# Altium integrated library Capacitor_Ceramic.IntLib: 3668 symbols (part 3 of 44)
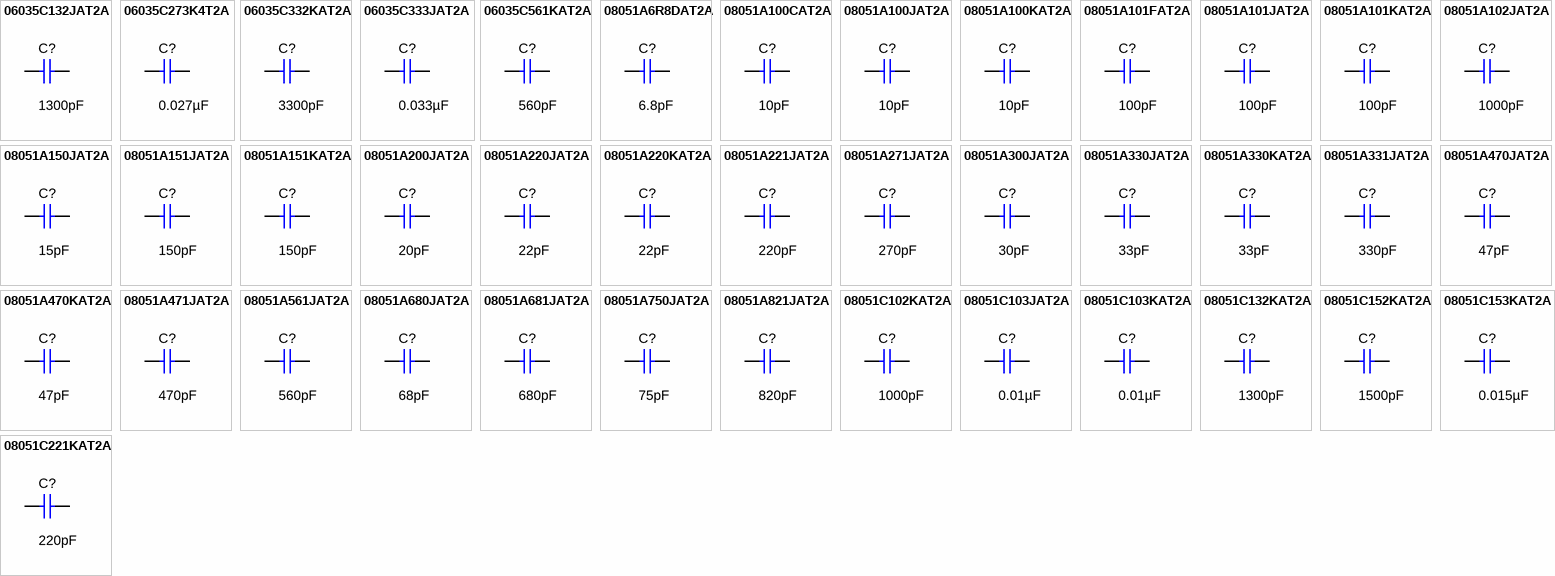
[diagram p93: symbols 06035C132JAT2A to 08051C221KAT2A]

## 06035C332KAT2A
designator C?  ValueDisplayed: 3300pF  (hidden comment: 06035C332KAT2A)
CAP, CERM, 3300 pF, 50 V,+/- 10%, X7R, 0603; Manufacturer: AVX; Polarized: N; CompType: Capacitor; Value: 3300pF; U/M: EA; Cap_F: 0.0000000033; Tolerance_%: 10; VDC_V: 50; Value2: 50V; TaMin_C: -55; TaMax_C: 125; Cap_Case: 0603; SizeArea_mm2: 1.28; SizeAreaWB_mm2: 4.68; SizeX_mm: 1.6; SizeY_mm: 0.8; SizeZ_mm: 1; AEC Category: Q200; Green_Lifecycle: Active; Green_REACh: Passed
signal-integrity model Cap
simulation model Cap
footprint 0603
footprint 0603M
footprint 0603L
footprint 0603_HV
footprint 0603S
pins: 1, 2

## 06035C333JAT2A
designator C?  ValueDisplayed: 0.033µF  (hidden comment: 06035C333JAT2A)
CAP, CERM, 0.033 µF, 50 V,+/- 5%, X7R, 0603; Manufacturer: AVX; Polarized: N; CompType: Capacitor; Value: 0.033uF; U/M: EA; Cap_F: 0.000000033; Tolerance_%: 5; VDC_V: 50; Value2: 50V; TaMin_C: -55; TaMax_C: 125; Cap_Case: 0603; SizeArea_mm2: 1.28; SizeAreaWB_mm2: 4.68; SizeX_mm: 1.6; SizeY_mm: 0.8; SizeZ_mm: 1; AEC Category: Q200; Green_Lifecycle: Active; Green_REACh: Passed
signal-integrity model Cap
simulation model Cap
footprint 0603
footprint 0603M
footprint 0603L
footprint 0603_HV
footprint 0603S
pins: 1, 2

## 06035C561KAT2A
designator C?  ValueDisplayed: 560pF  (hidden comment: 06035C561KAT2A)
CAP, CERM, 560 pF, 50 V,+/- 10%, X7R, 0603; Manufacturer: AVX; Polarized: N; CompType: Capacitor; Value: 560pF; U/M: EA; Cap_F: 0.00000000056; Tolerance_%: 10; VDC_V: 50; Value2: 50V; TaMin_C: -55; TaMax_C: 125; Cap_Case: 0603; SizeArea_mm2: 1.28; SizeAreaWB_mm2: 4.68; SizeX_mm: 1.6; SizeY_mm: 0.8; SizeZ_mm: 1; AEC Category: Q200; Green_Lifecycle: Not Set; Green_REACh: Incomplete
signal-integrity model Cap
simulation model Cap
footprint 0603
footprint 0603M
footprint 0603L
footprint 0603_HV
footprint 0603S
pins: 1, 2

## 08051A6R8DAT2A
designator C?  ValueDisplayed: 6.8pF  (hidden comment: 08051A6R8DAT2A)
CAP, CERM, 6.8 pF, 100 V,+/- 5%, C0G/NP0, 0805; Manufacturer: AVX; Polarized: N; CompType: Capacitor; Value: 6.8pF; U/M: EA; Cap_F: 0.0000000000068; Tolerance_%: 5; ESR_ohm: 2.045; Value1: 2.045 ohm; VDC_V: 100; Value2: 100V; TaMin_C: -55; TaMax_C: 125; Cap_Case: 0805; SizeArea_mm2: 2.5; SizeAreaWB_mm2: 6.75; SizeX_mm: 2; SizeY_mm: 1.25; SizeZ_mm: 1.45; AEC Category: Q200; Green_Lifecycle: Not Set; Green_REACh: Incomplete
signal-integrity model Cap
simulation model Cap
footprint 0805_HV
footprint 0805_HV1
footprint 0805
footprint 0805M
footprint 0805L
pins: 1, 2

## 08051A100CAT2A
designator C?  ValueDisplayed: 10pF  (hidden comment: 08051A100CAT2A)
CAP, CERM, 10 pF, 100 V,+/- 5%, C0G/NP0, 0805; Manufacturer: AVX; Polarized: N; CompType: Capacitor; Value: 10pF; U/M: EA; Cap_F: 0.00000000001; Tolerance_%: 5; ESR_ohm: 1.561; Value1: 1.561 ohm; VDC_V: 100; Value2: 100V; TaMin_C: -55; TaMax_C: 125; Cap_Case: 0805; SizeArea_mm2: 2.5; SizeAreaWB_mm2: 6.75; SizeX_mm: 2; SizeY_mm: 1.25; SizeZ_mm: 1.45; AEC Category: Q200; Green_Lifecycle: Not Set; Green_REACh: Incomplete
signal-integrity model Cap
simulation model Cap
footprint 0805_HV
footprint 0805_HV1
footprint 0805
footprint 0805M
footprint 0805L
pins: 1, 2

## 08051A100JAT2A
designator C?  ValueDisplayed: 10pF  (hidden comment: 08051A100JAT2A)
CAP, CERM, 10 pF, 100 V,+/- 5%, C0G/NP0, 0805; Manufacturer: AVX; Polarized: N; CompType: Capacitor; Value: 10pF; U/M: EA; Cap_F: 0.00000000001; Tolerance_%: 5; ESR_ohm: 1.561; Value1: 1.561 ohm; VDC_V: 100; Value2: 100V; TaMin_C: -55; TaMax_C: 125; Cap_Case: 0805; SizeArea_mm2: 2.5; SizeAreaWB_mm2: 6.75; SizeX_mm: 2; SizeY_mm: 1.25; SizeZ_mm: 1.45; AEC Category: Q200; Green_Lifecycle: Not Set; Green_REACh: Incomplete
signal-integrity model Cap
simulation model Cap
footprint 0805_HV
footprint 0805_HV1
footprint 0805
footprint 0805M
footprint 0805L
pins: 1, 2

## 08051A100KAT2A
designator C?  ValueDisplayed: 10pF  (hidden comment: 08051A100KAT2A)
CAP, CERM, 10 pF, 100 V,+/- 10%, C0G/NP0, 0805; Manufacturer: AVX; Polarized: N; CompType: Capacitor; Value: 10pF; U/M: EA; Cap_F: 0.00000000001; Tolerance_%: 10; ESR_ohm: 1.561; Value1: 1.561 ohm; VDC_V: 100; Value2: 100V; TaMin_C: -55; TaMax_C: 125; Cap_Case: 0805; SizeArea_mm2: 2.5; SizeAreaWB_mm2: 6.75; SizeX_mm: 2; SizeY_mm: 1.25; SizeZ_mm: 1.45; AEC Category: Q200; Green_Lifecycle: Not Set; Green_REACh: Incomplete
signal-integrity model Cap
simulation model Cap
footprint 0805_HV
footprint 0805_HV1
footprint 0805
footprint 0805M
footprint 0805L
pins: 1, 2

## 08051A101FAT2A
designator C?  ValueDisplayed: 100pF  (hidden comment: 08051A101FAT2A)
CAP, CERM, 100 pF, 100 V,+/- 1%, C0G/NP0, 0805; Manufacturer: AVX; Polarized: N; CompType: Capacitor; Value: 100pF; U/M: EA; Cap_F: 0.0000000001; Tolerance_%: 1; ESR_ohm: 0.356; Value1: 0.356 ohm; VDC_V: 100; Value2: 100V; TaMin_C: -55; TaMax_C: 125; Cap_Case: 0805; SizeArea_mm2: 2.5; SizeAreaWB_mm2: 6.75; SizeX_mm: 2; SizeY_mm: 1.25; SizeZ_mm: 1.45; AEC Category: Q200; Green_Lifecycle: Not Set; Green_REACh: Incomplete
signal-integrity model Cap
simulation model Cap
footprint 0805_HV
footprint 0805_HV1
footprint 0805
footprint 0805M
footprint 0805L
pins: 1, 2

## 08051A101JAT2A
designator C?  ValueDisplayed: 100pF  (hidden comment: 08051A101JAT2A)
CAP, CERM, 100 pF, 100 V,+/- 5%, C0G/NP0, 0805; Manufacturer: AVX; Polarized: N; CompType: Capacitor; Value: 100pF; U/M: EA; Cap_F: 0.0000000001; Tolerance_%: 5; ESR_ohm: 0.356; Value1: 0.356 ohm; VDC_V: 100; Value2: 100V; TaMin_C: -55; TaMax_C: 125; Cap_Case: 0805; SizeArea_mm2: 2.5; SizeAreaWB_mm2: 6.75; SizeX_mm: 2; SizeY_mm: 1.25; SizeZ_mm: 1.45; AEC Category: Q200; Green_Lifecycle: Not Set; Green_REACh: Incomplete
signal-integrity model Cap
simulation model Cap
footprint 0805_HV
footprint 0805_HV1
footprint 0805
footprint 0805M
footprint 0805L
pins: 1, 2

## 08051A101KAT2A
designator C?  ValueDisplayed: 100pF  (hidden comment: 08051A101KAT2A)
CAP, CERM, 100 pF, 100 V,+/- 10%, C0G/NP0, 0805; Manufacturer: AVX; Polarized: N; CompType: Capacitor; Value: 100pF; U/M: EA; Cap_F: 0.0000000001; Tolerance_%: 10; ESR_ohm: 0.356; Value1: 0.356 ohm; VDC_V: 100; Value2: 100V; TaMin_C: -55; TaMax_C: 125; Cap_Case: 0805; SizeArea_mm2: 2.5; SizeAreaWB_mm2: 6.75; SizeX_mm: 2; SizeY_mm: 1.25; SizeZ_mm: 1.45; AEC Category: Q200; Green_Lifecycle: Not Set; Green_REACh: Incomplete
signal-integrity model Cap
simulation model Cap
footprint 0805_HV
footprint 0805_HV1
footprint 0805
footprint 0805M
footprint 0805L
pins: 1, 2

## 08051A102JAT2A
designator C?  ValueDisplayed: 1000pF  (hidden comment: 08051A102JAT2A)
CAP, CERM, 1000 pF, 100 V,+/- 5%, C0G/NP0, 0805; Manufacturer: AVX; Polarized: N; CompType: Capacitor; Value: 1000pF; U/M: EA; Cap_F: 0.000000001; Tolerance_%: 5; ESR_ohm: 0.112; Value1: 0.112 ohm; VDC_V: 100; Value2: 100V; TaMin_C: -55; TaMax_C: 125; Cap_Case: 0805; SizeArea_mm2: 2.5; SizeAreaWB_mm2: 6.75; SizeX_mm: 2; SizeY_mm: 1.25; SizeZ_mm: 1.45; AEC Category: Q200; Green_Lifecycle: Not Set; Green_REACh: Incomplete
signal-integrity model Cap
simulation model Cap
footprint 0805_HV
footprint 0805_HV1
footprint 0805
footprint 0805M
footprint 0805L
pins: 1, 2

## 08051A150JAT2A
designator C?  ValueDisplayed: 15pF  (hidden comment: 08051A150JAT2A)
CAP, CERM, 15 pF, 100 V,+/- 5%, C0G/NP0, 0805; Manufacturer: AVX; Polarized: N; CompType: Capacitor; Value: 15pF; U/M: EA; Cap_F: 0.000000000015; Tolerance_%: 5; ESR_ohm: 1.185; Value1: 1.185 ohm; VDC_V: 100; Value2: 100V; TaMin_C: -55; TaMax_C: 125; Cap_Case: 0805; SizeArea_mm2: 2.5; SizeAreaWB_mm2: 6.75; SizeX_mm: 2; SizeY_mm: 1.25; SizeZ_mm: 1.45; AEC Category: Q200; Green_Lifecycle: Not Set; Green_REACh: Incomplete
signal-integrity model Cap
simulation model Cap
footprint 0805_HV
footprint 0805_HV1
footprint 0805
footprint 0805M
footprint 0805L
pins: 1, 2

## 08051A151JAT2A
designator C?  ValueDisplayed: 150pF  (hidden comment: 08051A151JAT2A)
CAP, CERM, 150 pF, 100 V,+/- 5%, C0G/NP0, 0805; Manufacturer: AVX; Polarized: N; CompType: Capacitor; Value: 150pF; U/M: EA; Cap_F: 0.00000000015; Tolerance_%: 5; ESR_ohm: 0.279; Value1: 0.279 ohm; VDC_V: 100; Value2: 100V; TaMin_C: -55; TaMax_C: 125; Cap_Case: 0805; SizeArea_mm2: 2.5; SizeAreaWB_mm2: 6.75; SizeX_mm: 2; SizeY_mm: 1.25; SizeZ_mm: 1.45; AEC Category: Q200; Green_Lifecycle: Not Set; Green_REACh: Incomplete
signal-integrity model Cap
simulation model Cap
footprint 0805_HV
footprint 0805_HV1
footprint 0805
footprint 0805M
footprint 0805L
pins: 1, 2

## 08051A151KAT2A
designator C?  ValueDisplayed: 150pF  (hidden comment: 08051A151KAT2A)
CAP, CERM, 150 pF, 100 V,+/- 10%, C0G/NP0, 0805; Manufacturer: AVX; Polarized: N; CompType: Capacitor; Value: 150pF; U/M: EA; Cap_F: 0.00000000015; Tolerance_%: 10; ESR_ohm: 0.279; Value1: 0.279 ohm; VDC_V: 100; Value2: 100V; TaMin_C: -55; TaMax_C: 125; Cap_Case: 0805; SizeArea_mm2: 2.5; SizeAreaWB_mm2: 6.75; SizeX_mm: 2; SizeY_mm: 1.25; SizeZ_mm: 1.45; AEC Category: Q200; Green_Lifecycle: Not Set; Green_REACh: Incomplete
signal-integrity model Cap
simulation model Cap
footprint 0805_HV
footprint 0805_HV1
footprint 0805
footprint 0805M
footprint 0805L
pins: 1, 2

## 08051A200JAT2A
designator C?  ValueDisplayed: 20pF  (hidden comment: 08051A200JAT2A)
CAP, CERM, 20 pF, 100 V,+/- 5%, C0G/NP0, 0805; Manufacturer: AVX; Polarized: N; CompType: Capacitor; Value: 20pF; U/M: EA; Cap_F: 0.00000000002; Tolerance_%: 5; ESR_ohm: 0.92; Value1: 0.92 ohm; VDC_V: 100; Value2: 100V; TaMin_C: -55; TaMax_C: 125; Cap_Case: 0805; SizeArea_mm2: 2.5; SizeAreaWB_mm2: 6.75; SizeX_mm: 2; SizeY_mm: 1.25; SizeZ_mm: 1.45; AEC Category: Q200; Green_Lifecycle: Not Set; Green_REACh: Incomplete
signal-integrity model Cap
simulation model Cap
footprint 0805_HV
footprint 0805_HV1
footprint 0805
footprint 0805M
footprint 0805L
pins: 1, 2

## 08051A220JAT2A
designator C?  ValueDisplayed: 22pF  (hidden comment: 08051A220JAT2A)
CAP, CERM, 22 pF, 100 V,+/- 5%, C0G/NP0, 0805; Manufacturer: AVX; Polarized: N; CompType: Capacitor; Value: 22pF; U/M: EA; Cap_F: 0.000000000022; Tolerance_%: 5; ESR_ohm: 0.92; Value1: 0.92 ohm; VDC_V: 100; Value2: 100V; TaMin_C: -55; TaMax_C: 125; Cap_Case: 0805; SizeArea_mm2: 2.5; SizeAreaWB_mm2: 6.75; SizeX_mm: 2; SizeY_mm: 1.25; SizeZ_mm: 1.45; AEC Category: Q200; Green_Lifecycle: Not Set; Green_REACh: Incomplete
signal-integrity model Cap
simulation model Cap
footprint 0805_HV
footprint 0805_HV1
footprint 0805
footprint 0805M
footprint 0805L
pins: 1, 2

## 08051A220KAT2A
designator C?  ValueDisplayed: 22pF  (hidden comment: 08051A220KAT2A)
CAP, CERM, 22 pF, 100 V,+/- 10%, C0G/NP0, 0805; Manufacturer: AVX; Polarized: N; CompType: Capacitor; Value: 22pF; U/M: EA; Cap_F: 0.000000000022; Tolerance_%: 10; ESR_ohm: 0.92; Value1: 0.92 ohm; VDC_V: 100; Value2: 100V; TaMin_C: -55; TaMax_C: 125; Cap_Case: 0805; SizeArea_mm2: 2.5; SizeAreaWB_mm2: 6.75; SizeX_mm: 2; SizeY_mm: 1.25; SizeZ_mm: 1.45; AEC Category: Q200; Green_Lifecycle: Not Set; Green_REACh: Incomplete
signal-integrity model Cap
simulation model Cap
footprint 0805_HV
footprint 0805_HV1
footprint 0805
footprint 0805M
footprint 0805L
pins: 1, 2

## 08051A221JAT2A
designator C?  ValueDisplayed: 220pF  (hidden comment: 08051A221JAT2A)
CAP, CERM, 220 pF, 100 V,+/- 5%, C0G/NP0, 0805; Manufacturer: AVX; Polarized: N; CompType: Capacitor; Value: 220pF; U/M: EA; Cap_F: 0.00000000022; Tolerance_%: 5; ESR_ohm: 0.23; Value1: 0.23 ohm; VDC_V: 100; Value2: 100V; TaMin_C: -55; TaMax_C: 125; Cap_Case: 0805; SizeArea_mm2: 2.5; SizeAreaWB_mm2: 6.75; SizeX_mm: 2; SizeY_mm: 1.25; SizeZ_mm: 1.45; AEC Category: Q200; Green_Lifecycle: Not Set; Green_REACh: Incomplete
signal-integrity model Cap
simulation model Cap
footprint 0805_HV
footprint 0805_HV1
footprint 0805
footprint 0805M
footprint 0805L
pins: 1, 2

## 08051A271JAT2A
designator C?  ValueDisplayed: 270pF  (hidden comment: 08051A271JAT2A)
CAP, CERM, 270 pF, 100 V,+/- 5%, C0G/NP0, 0805; Manufacturer: AVX; Polarized: N; CompType: Capacitor; Value: 270pF; U/M: EA; Cap_F: 0.00000000027; Tolerance_%: 5; ESR_ohm: 0.208; Value1: 0.208 ohm; VDC_V: 100; Value2: 100V; TaMin_C: -55; TaMax_C: 125; Cap_Case: 0805; SizeArea_mm2: 2.5; SizeAreaWB_mm2: 6.75; SizeX_mm: 2; SizeY_mm: 1.25; SizeZ_mm: 1.45; AEC Category: Q200; Green_Lifecycle: Not Set; Green_REACh: Incomplete
signal-integrity model Cap
simulation model Cap
footprint 0805_HV
footprint 0805_HV1
footprint 0805
footprint 0805M
footprint 0805L
pins: 1, 2

## 08051A300JAT2A
designator C?  ValueDisplayed: 30pF  (hidden comment: 08051A300JAT2A)
CAP, CERM, 30 pF, 100 V,+/- 5%, C0G/NP0, 0805; Manufacturer: AVX; Polarized: N; CompType: Capacitor; Value: 30pF; U/M: EA; Cap_F: 0.00000000003; Tolerance_%: 5; ESR_ohm: 0.708; Value1: 0.708 ohm; VDC_V: 100; Value2: 100V; TaMin_C: -55; TaMax_C: 125; Cap_Case: 0805; SizeArea_mm2: 2.5; SizeAreaWB_mm2: 6.75; SizeX_mm: 2; SizeY_mm: 1.25; SizeZ_mm: 1.45; AEC Category: Q200; Green_Lifecycle: Not Set; Green_REACh: Incomplete
signal-integrity model Cap
simulation model Cap
footprint 0805_HV
footprint 0805_HV1
footprint 0805
footprint 0805M
footprint 0805L
pins: 1, 2

## 08051A330JAT2A
designator C?  ValueDisplayed: 33pF  (hidden comment: 08051A330JAT2A)
CAP, CERM, 33 pF, 100 V,+/- 5%, C0G/NP0, 0805; Manufacturer: AVX; Polarized: N; CompType: Capacitor; Value: 33pF; U/M: EA; Cap_F: 0.000000000033; Tolerance_%: 5; ESR_ohm: 0.708; Value1: 0.708 ohm; VDC_V: 100; Value2: 100V; TaMin_C: -55; TaMax_C: 125; Cap_Case: 0805; SizeArea_mm2: 2.5; SizeAreaWB_mm2: 6.75; SizeX_mm: 2; SizeY_mm: 1.25; SizeZ_mm: 1.45; AEC Category: Q200; Green_Lifecycle: Not Set; Green_REACh: Incomplete
signal-integrity model Cap
simulation model Cap
footprint 0805_HV
footprint 0805_HV1
footprint 0805
footprint 0805M
footprint 0805L
pins: 1, 2

## 08051A330KAT2A
designator C?  ValueDisplayed: 33pF  (hidden comment: 08051A330KAT2A)
CAP, CERM, 33 pF, 100 V,+/- 10%, C0G/NP0, 0805; Manufacturer: AVX; Polarized: N; CompType: Capacitor; Value: 33pF; U/M: EA; Cap_F: 0.000000000033; Tolerance_%: 10; ESR_ohm: 0.708; Value1: 0.708 ohm; VDC_V: 100; Value2: 100V; TaMin_C: -55; TaMax_C: 125; Cap_Case: 0805; SizeArea_mm2: 2.5; SizeAreaWB_mm2: 6.75; SizeX_mm: 2; SizeY_mm: 1.25; SizeZ_mm: 1.45; AEC Category: Q200; Green_Lifecycle: Not Set; Green_REACh: Incomplete
signal-integrity model Cap
simulation model Cap
footprint 0805_HV
footprint 0805_HV1
footprint 0805
footprint 0805M
footprint 0805L
pins: 1, 2

## 08051A331JAT2A
designator C?  ValueDisplayed: 330pF  (hidden comment: 08051A331JAT2A)
CAP, CERM, 330 pF, 100 V,+/- 5%, C0G/NP0, 0805; Manufacturer: AVX; Polarized: N; CompType: Capacitor; Value: 330pF; U/M: EA; Cap_F: 0.00000000033; Tolerance_%: 5; ESR_ohm: 0.185; Value1: 0.185 ohm; VDC_V: 100; Value2: 100V; TaMin_C: -55; TaMax_C: 125; Cap_Case: 0805; SizeArea_mm2: 2.5; SizeAreaWB_mm2: 6.75; SizeX_mm: 2; SizeY_mm: 1.25; SizeZ_mm: 1.45; AEC Category: Q200; Green_Lifecycle: Not Set; Green_REACh: Incomplete
signal-integrity model Cap
simulation model Cap
footprint 0805_HV
footprint 0805_HV1
footprint 0805
footprint 0805M
footprint 0805L
pins: 1, 2

## 08051A470JAT2A
designator C?  ValueDisplayed: 47pF  (hidden comment: 08051A470JAT2A)
CAP, CERM, 47 pF, 100 V,+/- 5%, C0G/NP0, 0805; Manufacturer: AVX; Polarized: N; CompType: Capacitor; Value: 47pF; U/M: EA; Cap_F: 0.000000000047; Tolerance_%: 5; ESR_ohm: 0.566; Value1: 0.566 ohm; VDC_V: 100; Value2: 100V; TaMin_C: -55; TaMax_C: 125; Cap_Case: 0805; SizeArea_mm2: 2.5; SizeAreaWB_mm2: 6.75; SizeX_mm: 2; SizeY_mm: 1.25; SizeZ_mm: 1.45; AEC Category: Q200; Green_Lifecycle: Active; Green_REACh: Passed
signal-integrity model Cap
simulation model Cap
footprint 0805_HV
footprint 0805_HV1
footprint 0805
footprint 0805M
footprint 0805L
pins: 1, 2

## 08051A470KAT2A
designator C?  ValueDisplayed: 47pF  (hidden comment: 08051A470KAT2A)
CAP, CERM, 47 pF, 100 V,+/- 10%, C0G/NP0, 0805; Manufacturer: AVX; Polarized: N; CompType: Capacitor; Value: 47pF; U/M: EA; Cap_F: 0.000000000047; Tolerance_%: 10; ESR_ohm: 0.566; Value1: 0.566 ohm; VDC_V: 100; Value2: 100V; TaMin_C: -55; TaMax_C: 125; Cap_Case: 0805; SizeArea_mm2: 2.5; SizeAreaWB_mm2: 6.75; SizeX_mm: 2; SizeY_mm: 1.25; SizeZ_mm: 1.45; AEC Category: Q200; Green_Lifecycle: Not Set; Green_REACh: Incomplete
signal-integrity model Cap
simulation model Cap
footprint 0805_HV
footprint 0805_HV1
footprint 0805
footprint 0805M
footprint 0805L
pins: 1, 2

## 08051A471JAT2A
designator C?  ValueDisplayed: 470pF  (hidden comment: 08051A471JAT2A)
CAP, CERM, 470 pF, 100 V,+/- 5%, C0G/NP0, 0805; Manufacturer: AVX; Polarized: N; CompType: Capacitor; Value: 470pF; U/M: EA; Cap_F: 0.00000000047; Tolerance_%: 5; ESR_ohm: 0.159; Value1: 0.159 ohm; VDC_V: 100; Value2: 100V; TaMin_C: -55; TaMax_C: 125; Cap_Case: 0805; SizeArea_mm2: 2.5; SizeAreaWB_mm2: 6.75; SizeX_mm: 2; SizeY_mm: 1.25; SizeZ_mm: 1.45; AEC Category: Q200; Green_Lifecycle: Active; Green_REACh: Passed
signal-integrity model Cap
simulation model Cap
footprint 0805_HV
footprint 0805_HV1
footprint 0805
footprint 0805M
footprint 0805L
pins: 1, 2

## 08051A561JAT2A
designator C?  ValueDisplayed: 560pF  (hidden comment: 08051A561JAT2A)
CAP, CERM, 560 pF, 100 V,+/- 5%, C0G/NP0, 0805; Manufacturer: AVX; Polarized: N; CompType: Capacitor; Value: 560pF; U/M: EA; Cap_F: 0.00000000056; Tolerance_%: 5; ESR_ohm: 0.147; Value1: 0.147 ohm; VDC_V: 100; Value2: 100V; TaMin_C: -55; TaMax_C: 125; Cap_Case: 0805; SizeArea_mm2: 2.5; SizeAreaWB_mm2: 6.75; SizeX_mm: 2; SizeY_mm: 1.25; SizeZ_mm: 1.45; AEC Category: Q200; Green_Lifecycle: Active; Green_REACh: Passed
signal-integrity model Cap
simulation model Cap
footprint 0805_HV
footprint 0805_HV1
footprint 0805
footprint 0805M
footprint 0805L
pins: 1, 2

## 08051A680JAT2A
designator C?  ValueDisplayed: 68pF  (hidden comment: 08051A680JAT2A)
CAP, CERM, 68 pF, 100 V,+/- 5%, C0G/NP0, 0805; Manufacturer: AVX; Polarized: N; CompType: Capacitor; Value: 68pF; U/M: EA; Cap_F: 0.000000000068; Tolerance_%: 5; ESR_ohm: 0.45; Value1: 0.45 ohm; VDC_V: 100; Value2: 100V; TaMin_C: -55; TaMax_C: 125; Cap_Case: 0805; SizeArea_mm2: 2.5; SizeAreaWB_mm2: 6.75; SizeX_mm: 2; SizeY_mm: 1.25; SizeZ_mm: 1.45; AEC Category: Q200; Green_Lifecycle: Not Set; Green_REACh: Incomplete
signal-integrity model Cap
simulation model Cap
footprint 0805_HV
footprint 0805_HV1
footprint 0805
footprint 0805M
footprint 0805L
pins: 1, 2

## 08051A681JAT2A
designator C?  ValueDisplayed: 680pF  (hidden comment: 08051A681JAT2A)
CAP, CERM, 680 pF, 100 V,+/- 5%, C0G/NP0, 0805; Manufacturer: AVX; Polarized: N; CompType: Capacitor; Value: 680pF; U/M: EA; Cap_F: 0.00000000068; Tolerance_%: 5; ESR_ohm: 0.134; Value1: 0.134 ohm; VDC_V: 100; Value2: 100V; TaMin_C: -55; TaMax_C: 125; Cap_Case: 0805; SizeArea_mm2: 2.5; SizeAreaWB_mm2: 6.75; SizeX_mm: 2; SizeY_mm: 1.25; SizeZ_mm: 1.45; AEC Category: Q200; Green_Lifecycle: Not Set; Green_REACh: Incomplete
signal-integrity model Cap
simulation model Cap
footprint 0805_HV
footprint 0805_HV1
footprint 0805
footprint 0805M
footprint 0805L
pins: 1, 2

## 08051A750JAT2A
designator C?  ValueDisplayed: 75pF  (hidden comment: 08051A750JAT2A)
CAP, CERM, 75 pF, 100 V,+/- 5%, C0G/NP0, 0805; Manufacturer: AVX; Polarized: N; CompType: Capacitor; Value: 75pF; U/M: EA; Cap_F: 0.000000000075; Tolerance_%: 5; ESR_ohm: 0.401; Value1: 0.401 ohm; VDC_V: 100; Value2: 100V; TaMin_C: -55; TaMax_C: 125; Cap_Case: 0805; SizeArea_mm2: 2.5; SizeAreaWB_mm2: 6.75; SizeX_mm: 2; SizeY_mm: 1.25; SizeZ_mm: 1.45; AEC Category: Q200; Green_Lifecycle: Not Set; Green_REACh: Incomplete
signal-integrity model Cap
simulation model Cap
footprint 0805_HV
footprint 0805_HV1
footprint 0805
footprint 0805M
footprint 0805L
pins: 1, 2

## 08051A821JAT2A
designator C?  ValueDisplayed: 820pF  (hidden comment: 08051A821JAT2A)
CAP, CERM, 820 pF, 100 V,+/- 5%, C0G/NP0, 0805; Manufacturer: AVX; Polarized: N; CompType: Capacitor; Value: 820pF; U/M: EA; Cap_F: 0.00000000082; Tolerance_%: 5; ESR_ohm: 0.123; Value1: 0.123 ohm; VDC_V: 100; Value2: 100V; TaMin_C: -55; TaMax_C: 125; Cap_Case: 0805; SizeArea_mm2: 2.5; SizeAreaWB_mm2: 6.75; SizeX_mm: 2; SizeY_mm: 1.25; SizeZ_mm: 1.45; AEC Category: Q200; Green_Lifecycle: Not Set; Green_REACh: Incomplete
signal-integrity model Cap
simulation model Cap
footprint 0805_HV
footprint 0805_HV1
footprint 0805
footprint 0805M
footprint 0805L
pins: 1, 2

## 08051C102KAT2A
designator C?  ValueDisplayed: 1000pF  (hidden comment: 08051C102KAT2A)
CAP, CERM, 1000 pF, 100 V,+/- 10%, X7R, 0805; Manufacturer: AVX; Polarized: N; CompType: Capacitor; Value: 1000pF; U/M: EA; Cap_F: 0.000000001; Tolerance_%: 10; ESR_ohm: 0.29; Value1: 0.29 ohm; VDC_V: 100; Value2: 100V; TaMin_C: -55; TaMax_C: 125; Cap_Case: 0805; SizeArea_mm2: 2.5; SizeAreaWB_mm2: 6.75; SizeX_mm: 2; SizeY_mm: 1.25; SizeZ_mm: 1.45; AEC Category: Q200; Green_Lifecycle: Active; Green_REACh: Passed
signal-integrity model Cap
simulation model Cap
footprint 0805_HV
footprint 0805_HV1
footprint 0805
footprint 0805M
footprint 0805L
pins: 1, 2

## 08051C103JAT2A
designator C?  ValueDisplayed: 0.01µF  (hidden comment: 08051C103JAT2A)
CAP, CERM, 0.01 µF, 100 V,+/- 5%, X7R, 0805; Manufacturer: AVX; Polarized: N; CompType: Capacitor; Value: 0.01uF; U/M: EA; Cap_F: 0.00000001; Tolerance_%: 5; ESR_ohm: 0.078; Value1: 0.078 ohm; VDC_V: 100; Value2: 100V; TaMin_C: -55; TaMax_C: 125; Cap_Case: 0805; SizeArea_mm2: 2.5; SizeAreaWB_mm2: 6.75; SizeX_mm: 2; SizeY_mm: 1.25; SizeZ_mm: 1.45; AEC Category: Q200; Green_Lifecycle: Active; Green_REACh: Passed
signal-integrity model Cap
simulation model Cap
footprint 0805_HV
footprint 0805_HV1
footprint 0805
footprint 0805M
footprint 0805L
pins: 1, 2

## 08051C103KAT2A
designator C?  ValueDisplayed: 0.01µF  (hidden comment: 08051C103KAT2A)
CAP, CERM, 0.01 µF, 100 V,+/- 10%, X7R, 0805; Manufacturer: AVX; Polarized: N; CompType: Capacitor; Value: 0.01uF; U/M: EA; Cap_F: 0.00000001; Tolerance_%: 10; ESR_ohm: 0.078; Value1: 0.078 ohm; VDC_V: 100; Value2: 100V; TaMin_C: -55; TaMax_C: 125; Cap_Case: 0805; SizeArea_mm2: 2.5; SizeAreaWB_mm2: 6.75; SizeX_mm: 2; SizeY_mm: 1.25; SizeZ_mm: 1.45; AEC Category: Q200; Green_Lifecycle: Active; Green_REACh: Passed
signal-integrity model Cap
simulation model Cap
footprint 0805_HV
footprint 0805_HV1
footprint 0805
footprint 0805M
footprint 0805L
pins: 1, 2

## 08051C132KAT2A
designator C?  ValueDisplayed: 1300pF  (hidden comment: 08051C132KAT2A)
CAP, CERM, 1300 pF, 100 V,+/- 10%, X7R, 0805; Manufacturer: AVX; Polarized: N; CompType: Capacitor; Value: 1300pF; U/M: EA; Cap_F: 0.0000000013; Tolerance_%: 10; VDC_V: 100; Value2: 100V; TaMin_C: -55; TaMax_C: 125; Cap_Case: 0805; SizeArea_mm2: 2.5; SizeAreaWB_mm2: 6.75; SizeX_mm: 2; SizeY_mm: 1.25; SizeZ_mm: 1.45; AEC Category: Q200; Green_Lifecycle: Not Set; Green_REACh: Incomplete
signal-integrity model Cap
simulation model Cap
footprint 0805_HV
footprint 0805_HV1
footprint 0805
footprint 0805M
footprint 0805L
pins: 1, 2

## 08051C152KAT2A
designator C?  ValueDisplayed: 1500pF  (hidden comment: 08051C152KAT2A)
CAP, CERM, 1500 pF, 100 V,+/- 10%, X7R, 0805; Manufacturer: AVX; Polarized: N; CompType: Capacitor; Value: 1500pF; U/M: EA; Cap_F: 0.0000000015; Tolerance_%: 10; ESR_ohm: 0.229; Value1: 0.229 ohm; VDC_V: 100; Value2: 100V; TaMin_C: -55; TaMax_C: 125; Cap_Case: 0805; SizeArea_mm2: 2.5; SizeAreaWB_mm2: 6.75; SizeX_mm: 2; SizeY_mm: 1.25; SizeZ_mm: 1.45; AEC Category: Q200; Green_Lifecycle: Not Set; Green_REACh: Incomplete
signal-integrity model Cap
simulation model Cap
footprint 0805_HV
footprint 0805_HV1
footprint 0805
footprint 0805M
footprint 0805L
pins: 1, 2

## 08051C153KAT2A
designator C?  ValueDisplayed: 0.015µF  (hidden comment: 08051C153KAT2A)
CAP, CERM, 0.015 µF, 100 V,+/- 10%, X7R, 0805; Manufacturer: AVX; Polarized: N; CompType: Capacitor; Value: 0.015uF; U/M: EA; Cap_F: 0.000000015; Tolerance_%: 10; ESR_ohm: 0.063; Value1: 0.063 ohm; VDC_V: 100; Value2: 100V; TaMin_C: -55; TaMax_C: 125; Cap_Case: 0805; SizeArea_mm2: 2.5; SizeAreaWB_mm2: 6.75; SizeX_mm: 2; SizeY_mm: 1.25; SizeZ_mm: 1.45; AEC Category: Q200; Green_Lifecycle: Not Set; Green_REACh: Incomplete
signal-integrity model Cap
simulation model Cap
footprint 0805_HV
footprint 0805_HV1
footprint 0805
footprint 0805M
footprint 0805L
pins: 1, 2

## 08051C221KAT2A
designator C?  ValueDisplayed: 220pF  (hidden comment: 08051C221KAT2A)
CAP, CERM, 220 pF, 100 V,+/- 10%, X7R, 0805; Manufacturer: AVX; Polarized: N; CompType: Capacitor; Value: 220pF; U/M: EA; Cap_F: 0.00000000022; Tolerance_%: 10; ESR_ohm: 0.724; Value1: 0.724 ohm; VDC_V: 100; Value2: 100V; TaMin_C: -55; TaMax_C: 125; Cap_Case: 0805; SizeArea_mm2: 2.5; SizeAreaWB_mm2: 6.75; SizeX_mm: 2; SizeY_mm: 1.25; SizeZ_mm: 1.45; AEC Category: Q200; Green_Lifecycle: Not Set; Green_REACh: Incomplete
signal-integrity model Cap
simulation model Cap
footprint 0805_HV
footprint 0805_HV1
footprint 0805
footprint 0805M
footprint 0805L
pins: 1, 2

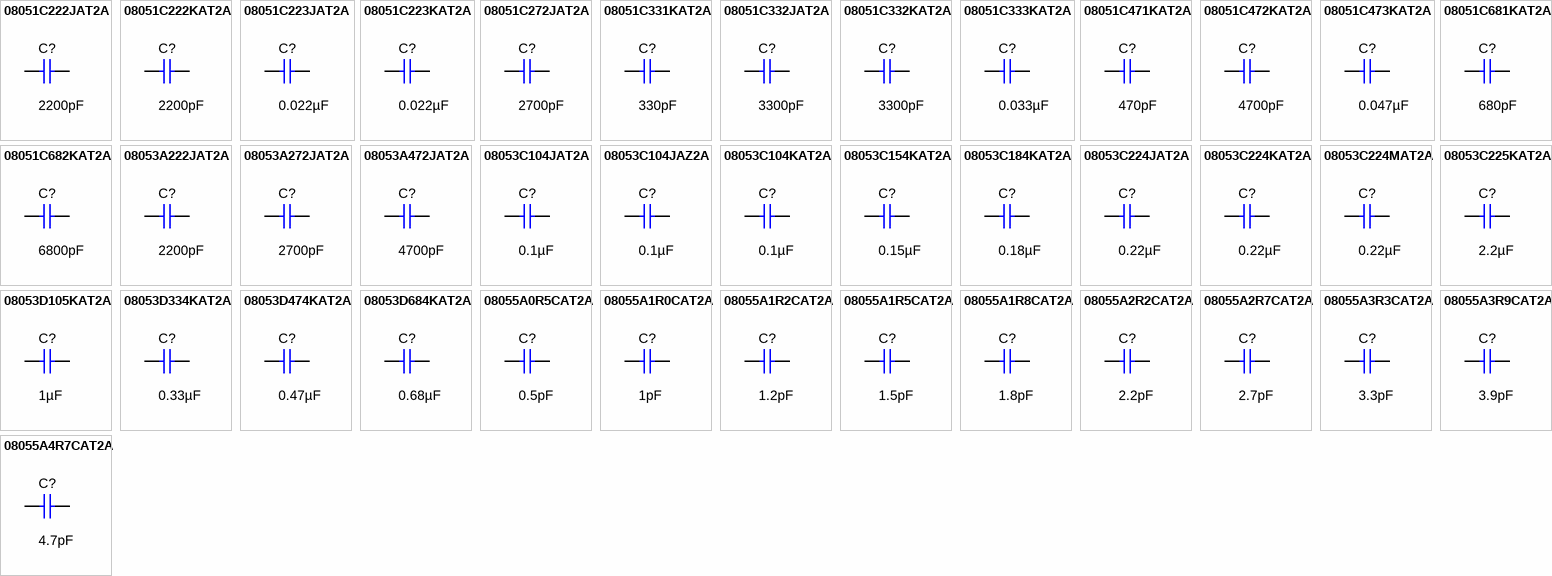
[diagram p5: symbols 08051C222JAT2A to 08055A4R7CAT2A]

## 08051C222JAT2A
designator C?  ValueDisplayed: 2200pF  (hidden comment: 08051C222JAT2A)
CAP, CERM, 2200 pF, 100 V,+/- 5%, X7R, 0805; Manufacturer: AVX; Polarized: N; CompType: Capacitor; Value: 2200pF; U/M: EA; Cap_F: 0.0000000022; Tolerance_%: 5; ESR_ohm: 0.183; Value1: 0.183 ohm; VDC_V: 100; Value2: 100V; TaMin_C: -55; TaMax_C: 125; Cap_Case: 0805; SizeArea_mm2: 2.5; SizeAreaWB_mm2: 6.75; SizeX_mm: 2; SizeY_mm: 1.25; SizeZ_mm: 1.45; AEC Category: Q200; Green_Lifecycle: Active; Green_REACh: Passed
signal-integrity model Cap
simulation model Cap
footprint 0805_HV
footprint 0805_HV1
footprint 0805
footprint 0805M
footprint 0805L
pins: 1, 2

## 08051C222KAT2A
designator C?  ValueDisplayed: 2200pF  (hidden comment: 08051C222KAT2A)
CAP, CERM, 2200 pF, 100 V,+/- 10%, X7R, 0805; Manufacturer: AVX; Polarized: N; CompType: Capacitor; Value: 2200pF; U/M: EA; Cap_F: 0.0000000022; Tolerance_%: 10; ESR_ohm: 0.183; Value1: 0.183 ohm; VDC_V: 100; Value2: 100V; TaMin_C: -55; TaMax_C: 125; Cap_Case: 0805; SizeArea_mm2: 2.5; SizeAreaWB_mm2: 6.75; SizeX_mm: 2; SizeY_mm: 1.25; SizeZ_mm: 1.45; AEC Category: Q200; Green_Lifecycle: Not Set; Green_REACh: Incomplete
signal-integrity model Cap
simulation model Cap
footprint 0805_HV
footprint 0805_HV1
footprint 0805
footprint 0805M
footprint 0805L
pins: 1, 2

## 08051C223JAT2A
designator C?  ValueDisplayed: 0.022µF  (hidden comment: 08051C223JAT2A)
CAP, CERM, 0.022 µF, 100 V,+/- 5%, X7R, 0805; Manufacturer: AVX; Polarized: N; CompType: Capacitor; Value: 0.022uF; U/M: EA; Cap_F: 0.000000022; Tolerance_%: 5; ESR_ohm: 0.052; Value1: 0.052 ohm; VDC_V: 100; Value2: 100V; TaMin_C: -55; TaMax_C: 125; Cap_Case: 0805; SizeArea_mm2: 2.5; SizeAreaWB_mm2: 6.75; SizeX_mm: 2; SizeY_mm: 1.25; SizeZ_mm: 1.45; AEC Category: Q200; Green_Lifecycle: Active; Green_REACh: Passed
signal-integrity model Cap
simulation model Cap
footprint 0805_HV
footprint 0805_HV1
footprint 0805
footprint 0805M
footprint 0805L
pins: 1, 2

## 08051C223KAT2A
designator C?  ValueDisplayed: 0.022µF  (hidden comment: 08051C223KAT2A)
CAP, CERM, 0.022 µF, 100 V,+/- 10%, X7R, 0805; Manufacturer: AVX; Polarized: N; CompType: Capacitor; Value: 0.022uF; U/M: EA; Cap_F: 0.000000022; Tolerance_%: 10; ESR_ohm: 0.052; Value1: 0.052 ohm; VDC_V: 100; Value2: 100V; TaMin_C: -55; TaMax_C: 125; Cap_Case: 0805; SizeArea_mm2: 2.5; SizeAreaWB_mm2: 6.75; SizeX_mm: 2; SizeY_mm: 1.25; SizeZ_mm: 1.45; AEC Category: Q200; Green_Lifecycle: Not Set; Green_REACh: Incomplete
signal-integrity model Cap
simulation model Cap
footprint 0805_HV
footprint 0805_HV1
footprint 0805
footprint 0805M
footprint 0805L
pins: 1, 2

## 08051C272JAT2A
designator C?  ValueDisplayed: 2700pF  (hidden comment: 08051C272JAT2A)
CAP, CERM, 2700 pF, 100 V,+/- 5%, X7R, 0805; Manufacturer: AVX; Polarized: N; CompType: Capacitor; Value: 2700pF; U/M: EA; Cap_F: 0.0000000027; Tolerance_%: 5; ESR_ohm: 0.163; Value1: 0.163 ohm; VDC_V: 100; Value2: 100V; TaMin_C: -55; TaMax_C: 125; Cap_Case: 0805; SizeArea_mm2: 2.5; SizeAreaWB_mm2: 6.75; SizeX_mm: 2; SizeY_mm: 1.25; SizeZ_mm: 1.45; AEC Category: Q200; Green_Lifecycle: Not Set; Green_REACh: Incomplete
signal-integrity model Cap
simulation model Cap
footprint 0805_HV
footprint 0805_HV1
footprint 0805
footprint 0805M
footprint 0805L
pins: 1, 2

## 08051C331KAT2A
designator C?  ValueDisplayed: 330pF  (hidden comment: 08051C331KAT2A)
CAP, CERM, 330 pF, 100 V,+/- 10%, X7R, 0805; Manufacturer: AVX; Polarized: N; CompType: Capacitor; Value: 330pF; U/M: EA; Cap_F: 0.00000000033; Tolerance_%: 10; ESR_ohm: 0.563; Value1: 0.563 ohm; VDC_V: 100; Value2: 100V; TaMin_C: -55; TaMax_C: 125; Cap_Case: 0805; SizeArea_mm2: 2.5; SizeAreaWB_mm2: 6.75; SizeX_mm: 2; SizeY_mm: 1.25; SizeZ_mm: 1.45; AEC Category: Q200; Green_Lifecycle: Not Set; Green_REACh: Incomplete
signal-integrity model Cap
simulation model Cap
footprint 0805_HV
footprint 0805_HV1
footprint 0805
footprint 0805M
footprint 0805L
pins: 1, 2

## 08051C332JAT2A
designator C?  ValueDisplayed: 3300pF  (hidden comment: 08051C332JAT2A)
CAP, CERM, 3300 pF, 100 V,+/- 5%, X7R, 0805; Manufacturer: AVX; Polarized: N; CompType: Capacitor; Value: 3300pF; U/M: EA; Cap_F: 0.0000000033; Tolerance_%: 5; ESR_ohm: 0.145; Value1: 0.145 ohm; VDC_V: 100; Value2: 100V; TaMin_C: -55; TaMax_C: 125; Cap_Case: 0805; SizeArea_mm2: 2.5; SizeAreaWB_mm2: 6.75; SizeX_mm: 2; SizeY_mm: 1.25; SizeZ_mm: 1.45; AEC Category: Q200; Green_Lifecycle: Not Set; Green_REACh: Incomplete
signal-integrity model Cap
simulation model Cap
footprint 0805_HV
footprint 0805_HV1
footprint 0805
footprint 0805M
footprint 0805L
pins: 1, 2

## 08051C332KAT2A
designator C?  ValueDisplayed: 3300pF  (hidden comment: 08051C332KAT2A)
CAP, CERM, 3300 pF, 100 V,+/- 10%, X7R, 0805; Manufacturer: AVX; Polarized: N; CompType: Capacitor; Value: 3300pF; U/M: EA; Cap_F: 0.0000000033; Tolerance_%: 10; ESR_ohm: 0.145; Value1: 0.145 ohm; VDC_V: 100; Value2: 100V; TaMin_C: -55; TaMax_C: 125; Cap_Case: 0805; SizeArea_mm2: 2.5; SizeAreaWB_mm2: 6.75; SizeX_mm: 2; SizeY_mm: 1.25; SizeZ_mm: 1.45; AEC Category: Q200; Green_Lifecycle: Not Set; Green_REACh: Incomplete
signal-integrity model Cap
simulation model Cap
footprint 0805_HV
footprint 0805_HV1
footprint 0805
footprint 0805M
footprint 0805L
pins: 1, 2

## 08051C333KAT2A
designator C?  ValueDisplayed: 0.033µF  (hidden comment: 08051C333KAT2A)
CAP, CERM, 0.033 µF, 100 V,+/- 10%, X7R, 0805; Manufacturer: AVX; Polarized: N; CompType: Capacitor; Value: 0.033uF; U/M: EA; Cap_F: 0.000000033; Tolerance_%: 10; ESR_ohm: 0.042; Value1: 0.042 ohm; VDC_V: 100; Value2: 100V; TaMin_C: -55; TaMax_C: 125; Cap_Case: 0805; SizeArea_mm2: 2.5; SizeAreaWB_mm2: 6.75; SizeX_mm: 2; SizeY_mm: 1.25; SizeZ_mm: 1.45; AEC Category: Q200; Green_Lifecycle: Not Set; Green_REACh: Incomplete
signal-integrity model Cap
simulation model Cap
footprint 0805_HV
footprint 0805_HV1
footprint 0805
footprint 0805M
footprint 0805L
pins: 1, 2

## 08051C471KAT2A
designator C?  ValueDisplayed: 470pF  (hidden comment: 08051C471KAT2A)
CAP, CERM, 470 pF, 100 V,+/- 10%, X7R, 0805; Manufacturer: AVX; Polarized: N; CompType: Capacitor; Value: 470pF; U/M: EA; Cap_F: 0.00000000047; Tolerance_%: 10; ESR_ohm: 0.454; Value1: 0.454 ohm; VDC_V: 100; Value2: 100V; TaMin_C: -55; TaMax_C: 125; Cap_Case: 0805; SizeArea_mm2: 2.5; SizeAreaWB_mm2: 6.75; SizeX_mm: 2; SizeY_mm: 1.25; SizeZ_mm: 1.45; AEC Category: Q200; Green_Lifecycle: Not Set; Green_REACh: Incomplete
signal-integrity model Cap
simulation model Cap
footprint 0805_HV
footprint 0805_HV1
footprint 0805
footprint 0805M
footprint 0805L
pins: 1, 2

## 08051C472KAT2A
designator C?  ValueDisplayed: 4700pF  (hidden comment: 08051C472KAT2A)
CAP, CERM, 4700 pF, 100 V,+/- 10%, X7R, 0805; Manufacturer: AVX; Polarized: N; CompType: Capacitor; Value: 4700pF; U/M: EA; Cap_F: 0.0000000047; Tolerance_%: 10; ESR_ohm: 0.119; Value1: 0.119 ohm; VDC_V: 100; Value2: 100V; TaMin_C: -55; TaMax_C: 125; Cap_Case: 0805; SizeArea_mm2: 2.5; SizeAreaWB_mm2: 6.75; SizeX_mm: 2; SizeY_mm: 1.25; SizeZ_mm: 1.45; AEC Category: Q200; Green_Lifecycle: Active; Green_REACh: Passed
signal-integrity model Cap
simulation model Cap
footprint 0805_HV
footprint 0805_HV1
footprint 0805
footprint 0805M
footprint 0805L
pins: 1, 2

## 08051C473KAT2A
designator C?  ValueDisplayed: 0.047µF  (hidden comment: 08051C473KAT2A)
CAP, CERM, 0.047 µF, 100 V,+/- 10%, X7R, 0805; Manufacturer: AVX; Polarized: N; CompType: Capacitor; Value: 0.047uF; U/M: EA; Cap_F: 0.000000047; Tolerance_%: 10; ESR_ohm: 0.035; Value1: 0.035 ohm; VDC_V: 100; Value2: 100V; TaMin_C: -55; TaMax_C: 125; Cap_Case: 0805; SizeArea_mm2: 2.5; SizeAreaWB_mm2: 6.75; SizeX_mm: 2; SizeY_mm: 1.25; SizeZ_mm: 1.45; AEC Category: Q200; Green_Lifecycle: Not Set; Green_REACh: Incomplete
signal-integrity model Cap
simulation model Cap
footprint 0805_HV
footprint 0805_HV1
footprint 0805
footprint 0805M
footprint 0805L
pins: 1, 2

## 08051C681KAT2A
designator C?  ValueDisplayed: 680pF  (hidden comment: 08051C681KAT2A)
CAP, CERM, 680 pF, 100 V,+/- 10%, X7R, 0805; Manufacturer: AVX; Polarized: N; CompType: Capacitor; Value: 680pF; U/M: EA; Cap_F: 0.00000000068; Tolerance_%: 10; ESR_ohm: 0.364; Value1: 0.364 ohm; VDC_V: 100; Value2: 100V; TaMin_C: -55; TaMax_C: 125; Cap_Case: 0805; SizeArea_mm2: 2.5; SizeAreaWB_mm2: 6.75; SizeX_mm: 2; SizeY_mm: 1.25; SizeZ_mm: 1.45; AEC Category: Q200; Green_Lifecycle: Active; Green_REACh: Passed
signal-integrity model Cap
simulation model Cap
footprint 0805_HV
footprint 0805_HV1
footprint 0805
footprint 0805M
footprint 0805L
pins: 1, 2

## 08051C682KAT2A
designator C?  ValueDisplayed: 6800pF  (hidden comment: 08051C682KAT2A)
CAP, CERM, 6800 pF, 100 V,+/- 10%, X7R, 0805; Manufacturer: AVX; Polarized: N; CompType: Capacitor; Value: 6800pF; U/M: EA; Cap_F: 0.0000000068; Tolerance_%: 10; ESR_ohm: 0.096; Value1: 0.096 ohm; VDC_V: 100; Value2: 100V; TaMin_C: -55; TaMax_C: 125; Cap_Case: 0805; SizeArea_mm2: 2.5; SizeAreaWB_mm2: 6.75; SizeX_mm: 2; SizeY_mm: 1.25; SizeZ_mm: 1.45; AEC Category: Q200; Green_Lifecycle: Not Set; Green_REACh: Incomplete
signal-integrity model Cap
simulation model Cap
footprint 0805_HV
footprint 0805_HV1
footprint 0805
footprint 0805M
footprint 0805L
pins: 1, 2

## 08053A222JAT2A
designator C?  ValueDisplayed: 2200pF  (hidden comment: 08053A222JAT2A)
CAP, CERM, 2200 pF, 25 V,+/- 5%, C0G/NP0, 0805; Manufacturer: AVX; Polarized: N; CompType: Capacitor; Value: 2200pF; U/M: EA; Cap_F: 0.0000000022; Tolerance_%: 5; ESR_ohm: 0.92; Value1: 0.92 ohm; VDC_V: 25; Value2: 25V; TaMin_C: -55; TaMax_C: 125; Cap_Case: 0805; SizeArea_mm2: 2.5; SizeAreaWB_mm2: 6.75; SizeX_mm: 2; SizeY_mm: 1.25; SizeZ_mm: 1.45; AEC Category: Q200; Green_Lifecycle: Not Set; Green_REACh: Incomplete
signal-integrity model Cap
simulation model Cap
footprint 0805_HV
footprint 0805_HV1
footprint 0805
footprint 0805M
footprint 0805L
pins: 1, 2

## 08053A272JAT2A
designator C?  ValueDisplayed: 2700pF  (hidden comment: 08053A272JAT2A)
CAP, CERM, 2700 pF, 25 V,+/- 5%, C0G/NP0, 0805; Manufacturer: AVX; Polarized: N; CompType: Capacitor; Value: 2700pF; U/M: EA; Cap_F: 0.0000000027; Tolerance_%: 5; ESR_ohm: 0.805; Value1: 0.805 ohm; VDC_V: 25; Value2: 25V; TaMin_C: -55; TaMax_C: 125; Cap_Case: 0805; SizeArea_mm2: 2.5; SizeAreaWB_mm2: 6.75; SizeX_mm: 2; SizeY_mm: 1.25; SizeZ_mm: 1.45; AEC Category: Q200; Green_Lifecycle: Not Set; Green_REACh: Incomplete
signal-integrity model Cap
simulation model Cap
footprint 0805_HV
footprint 0805_HV1
footprint 0805
footprint 0805M
footprint 0805L
pins: 1, 2

## 08053A472JAT2A
designator C?  ValueDisplayed: 4700pF  (hidden comment: 08053A472JAT2A)
CAP, CERM, 4700 pF, 25 V,+/- 5%, C0G/NP0, 0805; Manufacturer: AVX; Polarized: N; CompType: Capacitor; Value: 4700pF; U/M: EA; Cap_F: 0.0000000047; Tolerance_%: 5; ESR_ohm: 0.556; Value1: 0.556 ohm; VDC_V: 25; Value2: 25V; TaMin_C: -55; TaMax_C: 125; Cap_Case: 0805; SizeArea_mm2: 2.5; SizeAreaWB_mm2: 6.75; SizeX_mm: 2; SizeY_mm: 1.25; SizeZ_mm: 1.45; AEC Category: Q200; Green_Lifecycle: Active; Green_REACh: Passed
signal-integrity model Cap
simulation model Cap
footprint 0805_HV
footprint 0805_HV1
footprint 0805
footprint 0805M
footprint 0805L
pins: 1, 2

## 08053C104JAT2A
designator C?  ValueDisplayed: 0.1µF  (hidden comment: 08053C104JAT2A)
CAP, CERM, 0.1 µF, 25 V,+/- 5%, X7R, 0805; Manufacturer: AVX; Polarized: N; CompType: Capacitor; Value: 0.1uF; U/M: EA; Cap_F: 0.0000001; Tolerance_%: 5; VDC_V: 25; Value2: 25V; TaMin_C: -55; TaMax_C: 125; Cap_Case: 0805; SizeArea_mm2: 2.5; SizeAreaWB_mm2: 6.75; SizeX_mm: 2; SizeY_mm: 1.25; SizeZ_mm: 1.45; AEC Category: Q200
signal-integrity model Cap
simulation model Cap
footprint 0805_HV
footprint 0805_HV1
footprint 0805
footprint 0805M
footprint 0805L
pins: 1, 2

## 08053C104JAZ2A
designator C?  ValueDisplayed: 0.1µF  (hidden comment: 08053C104JAZ2A)
CAP, CERM, 0.1 µF, 25 V,+/- 5%, X7R, 0805; Manufacturer: AVX; Polarized: N; CompType: Capacitor; Value: 0.1uF; U/M: EA; Cap_F: 0.0000001; Tolerance_%: 5; VDC_V: 25; Value2: 25V; TaMin_C: -55; TaMax_C: 125; Cap_Case: 0805; SizeArea_mm2: 2.5; SizeAreaWB_mm2: 6.75; SizeX_mm: 2; SizeY_mm: 1.25; SizeZ_mm: 1.45; AEC Category: Q200
signal-integrity model Cap
simulation model Cap
footprint 0805_HV
footprint 0805_HV1
footprint 0805
footprint 0805M
footprint 0805L
pins: 1, 2

## 08053C104KAT2A
designator C?  ValueDisplayed: 0.1µF  (hidden comment: 08053C104KAT2A)
CAP, CERM, 0.1 µF, 25 V,+/- 10%, X7R, 0805; Manufacturer: AVX; Polarized: N; CompType: Capacitor; Value: 0.1uF; U/M: EA; Cap_F: 0.0000001; Tolerance_%: 10; ESR_ohm: 0.28; Value1: 0.28 ohm; VDC_V: 25; Value2: 25V; TaMin_C: -55; TaMax_C: 125; Cap_Case: 0805; SizeArea_mm2: 2.5; SizeAreaWB_mm2: 6.75; SizeX_mm: 2; SizeY_mm: 1.25; SizeZ_mm: 1.45; AEC Category: Q200; Green_Lifecycle: Active; Green_REACh: Passed
signal-integrity model Cap
simulation model Cap
footprint 0805_HV
footprint 0805_HV1
footprint 0805
footprint 0805M
footprint 0805L
pins: 1, 2

## 08053C154KAT2A
designator C?  ValueDisplayed: 0.15µF  (hidden comment: 08053C154KAT2A)
CAP, CERM, 0.15 µF, 25 V,+/- 10%, X7R, 0805; Manufacturer: AVX; Polarized: N; CompType: Capacitor; Value: 0.15uF; U/M: EA; Cap_F: 0.00000015; Tolerance_%: 10; ESR_ohm: 0.02; Value1: 0.02 ohm; VDC_V: 25; Value2: 25V; TaMin_C: -55; TaMax_C: 125; Cap_Case: 0805; SizeArea_mm2: 2.5; SizeAreaWB_mm2: 6.75; SizeX_mm: 2; SizeY_mm: 1.25; SizeZ_mm: 1.45; AEC Category: Q200; Green_Lifecycle: Active; Green_REACh: Passed
signal-integrity model Cap
simulation model Cap
footprint 0805_HV
footprint 0805_HV1
footprint 0805
footprint 0805M
footprint 0805L
pins: 1, 2

## 08053C184KAT2A
designator C?  ValueDisplayed: 0.18µF  (hidden comment: 08053C184KAT2A)
CAP, CERM, 0.18 µF, 25 V,+/- 10%, X7R, 0805; Manufacturer: AVX; Polarized: N; CompType: Capacitor; Value: 0.18uF; U/M: EA; Cap_F: 0.00000018; Tolerance_%: 10; ESR_ohm: 0.018; Value1: 0.018 ohm; VDC_V: 25; Value2: 25V; TaMin_C: -55; TaMax_C: 125; Cap_Case: 0805; SizeArea_mm2: 2.5; SizeAreaWB_mm2: 6.75; SizeX_mm: 2; SizeY_mm: 1.25; SizeZ_mm: 1.45; AEC Category: Q200; Green_Lifecycle: Not Set; Green_REACh: Incomplete
signal-integrity model Cap
simulation model Cap
footprint 0805_HV
footprint 0805_HV1
footprint 0805
footprint 0805M
footprint 0805L
pins: 1, 2

## 08053C224JAT2A
designator C?  ValueDisplayed: 0.22µF  (hidden comment: 08053C224JAT2A)
CAP, CERM, 0.22 µF, 25 V,+/- 5%, X7R, 0805; Manufacturer: AVX; Polarized: N; CompType: Capacitor; Value: 0.22uF; U/M: EA; Cap_F: 0.00000022; Tolerance_%: 5; ESR_ohm: 0.016; Value1: 0.016 ohm; VDC_V: 25; Value2: 25V; TaMin_C: -55; TaMax_C: 125; Cap_Case: 0805; SizeArea_mm2: 2.5; SizeAreaWB_mm2: 6.75; SizeX_mm: 2; SizeY_mm: 1.25; SizeZ_mm: 1.45; AEC Category: Q200; Green_Lifecycle: Active; Green_REACh: Passed
signal-integrity model Cap
simulation model Cap
footprint 0805_HV
footprint 0805_HV1
footprint 0805
footprint 0805M
footprint 0805L
pins: 1, 2

## 08053C224KAT2A
designator C?  ValueDisplayed: 0.22µF  (hidden comment: 08053C224KAT2A)
CAP, CERM, 0.22 µF, 25 V,+/- 10%, X7R, 0805; Manufacturer: AVX; Polarized: N; CompType: Capacitor; Value: 0.22uF; U/M: EA; Cap_F: 0.00000022; Tolerance_%: 10; ESR_ohm: 0.016; Value1: 0.016 ohm; VDC_V: 25; Value2: 25V; TaMin_C: -55; TaMax_C: 125; Cap_Case: 0805; SizeArea_mm2: 2.5; SizeAreaWB_mm2: 6.75; SizeX_mm: 2; SizeY_mm: 1.25; SizeZ_mm: 1.45; AEC Category: Q200; Green_Lifecycle: Not Set; Green_REACh: Incomplete
signal-integrity model Cap
simulation model Cap
footprint 0805_HV
footprint 0805_HV1
footprint 0805
footprint 0805M
footprint 0805L
pins: 1, 2

## 08053C224MAT2A
designator C?  ValueDisplayed: 0.22µF  (hidden comment: 08053C224MAT2A)
CAP, CERM, 0.22 µF, 25 V,+/- 20%, X7R, 0805; Manufacturer: AVX; Polarized: N; CompType: Capacitor; Value: 0.22uF; U/M: EA; Cap_F: 0.00000022; Tolerance_%: 20; ESR_ohm: 0.016; Value1: 0.016 ohm; VDC_V: 25; Value2: 25V; TaMin_C: -55; TaMax_C: 125; Cap_Case: 0805; SizeArea_mm2: 2.5; SizeAreaWB_mm2: 6.75; SizeX_mm: 2; SizeY_mm: 1.25; SizeZ_mm: 1.45; AEC Category: Q200; Green_Lifecycle: Not Set; Green_REACh: Incomplete
signal-integrity model Cap
simulation model Cap
footprint 0805_HV
footprint 0805_HV1
footprint 0805
footprint 0805M
footprint 0805L
pins: 1, 2

## 08053C225KAT2A
designator C?  ValueDisplayed: 2.2µF  (hidden comment: 08053C225KAT2A)
CAP, CERM, 2.2 µF, 25 V,+/- 10%, X7R, 0805; Manufacturer: AVX; Polarized: N; CompType: Capacitor; Value: 2.2uF; U/M: EA; Cap_F: 0.0000022; Tolerance_%: 10; VDC_V: 25; Value2: 25V; TaMin_C: -55; TaMax_C: 125; Cap_Case: 0805; SizeArea_mm2: 2.5; SizeAreaWB_mm2: 6.75; SizeX_mm: 2; SizeY_mm: 1.25; SizeZ_mm: 1.5; AEC Category: Q200; Green_Lifecycle: Not Set; Green_REACh: Incomplete
signal-integrity model Cap
simulation model Cap
footprint 0805_150
pins: 1, 2

## 08053D105KAT2A
designator C?  ValueDisplayed: 1µF  (hidden comment: 08053D105KAT2A)
CAP, CERM, 1 µF, 25 V,+/- 10%, X5R, 0805; Manufacturer: AVX; Polarized: N; CompType: Capacitor; Value: 1uF; U/M: EA; Cap_F: 0.000001; Tolerance_%: 10; ESR_ohm: 0.012; Value1: 0.012 ohm; VDC_V: 25; Value2: 25V; TaMin_C: -55; TaMax_C: 85; Cap_Case: 0805; SizeArea_mm2: 2.5; SizeAreaWB_mm2: 6.75; SizeX_mm: 2; SizeY_mm: 1.25; SizeZ_mm: 1.45; AEC Category: Q200; Green_Lifecycle: Active; Green_REACh: Passed
signal-integrity model Cap
simulation model Cap
footprint 0805_HV
footprint 0805_HV1
footprint 0805
footprint 0805M
footprint 0805L
pins: 1, 2

## 08053D334KAT2A
designator C?  ValueDisplayed: 0.33µF  (hidden comment: 08053D334KAT2A)
CAP, CERM, 0.33 µF, 25 V,+/- 10%, X5R, 0805; Manufacturer: AVX; Polarized: N; CompType: Capacitor; Value: 0.33uF; U/M: EA; Cap_F: 0.00000033; Tolerance_%: 10; ESR_ohm: 0.02; Value1: 0.02 ohm; VDC_V: 25; Value2: 25V; TaMin_C: -55; TaMax_C: 85; Cap_Case: 0805; SizeArea_mm2: 2.5; SizeAreaWB_mm2: 6.75; SizeX_mm: 2; SizeY_mm: 1.25; SizeZ_mm: 1.45; AEC Category: Q200; Green_Lifecycle: Not Set; Green_REACh: Incomplete
signal-integrity model Cap
simulation model Cap
footprint 0805_HV
footprint 0805_HV1
footprint 0805
footprint 0805M
footprint 0805L
pins: 1, 2

## 08053D474KAT2A
designator C?  ValueDisplayed: 0.47µF  (hidden comment: 08053D474KAT2A)
CAP, CERM, 0.47 µF, 25 V,+/- 10%, X5R, 0805; Manufacturer: AVX; Polarized: N; CompType: Capacitor; Value: 0.47uF; U/M: EA; Cap_F: 0.00000047; Tolerance_%: 10; ESR_ohm: 0.017; Value1: 0.017 ohm; VDC_V: 25; Value2: 25V; TaMin_C: -55; TaMax_C: 85; Cap_Case: 0805; SizeArea_mm2: 2.5; SizeAreaWB_mm2: 6.75; SizeX_mm: 2; SizeY_mm: 1.25; SizeZ_mm: 1.45; AEC Category: Q200; Green_Lifecycle: Active; Green_REACh: Passed
signal-integrity model Cap
simulation model Cap
footprint 0805_HV
footprint 0805_HV1
footprint 0805
footprint 0805M
footprint 0805L
pins: 1, 2

## 08053D684KAT2A
designator C?  ValueDisplayed: 0.68µF  (hidden comment: 08053D684KAT2A)
CAP, CERM, 0.68 µF, 25 V,+/- 10%, X5R, 0805; Manufacturer: AVX; Polarized: N; CompType: Capacitor; Value: 0.68uF; U/M: EA; Cap_F: 0.00000068; Tolerance_%: 10; ESR_ohm: 0.015; Value1: 0.015 ohm; VDC_V: 25; Value2: 25V; TaMin_C: -55; TaMax_C: 85; Cap_Case: 0805; SizeArea_mm2: 2.5; SizeAreaWB_mm2: 6.75; SizeX_mm: 2; SizeY_mm: 1.25; SizeZ_mm: 1.45; AEC Category: Q200; Green_Lifecycle: Not Set; Green_REACh: Incomplete
signal-integrity model Cap
simulation model Cap
footprint 0805_HV
footprint 0805_HV1
footprint 0805
footprint 0805M
footprint 0805L
pins: 1, 2

## 08055A0R5CAT2A
designator C?  ValueDisplayed: 0.5pF  (hidden comment: 08055A0R5CAT2A)
CAP, CERM, 0.5 pF, 50 V,+/- 50%, C0G/NP0, 0805; Manufacturer: AVX; Polarized: N; CompType: Capacitor; Value: 0.5pF; U/M: EA; Cap_F: 0.0000000000005; Tolerance_%: 50; ESR_ohm: 15.98; Value1: 15.98 ohm; Value2: 50V; TaMin_C: -55; TaMax_C: 125; Cap_Case: 0805; SizeArea_mm2: 2.5; SizeAreaWB_mm2: 6.75; SizeX_mm: 2; SizeY_mm: 1.25; SizeZ_mm: 1.45; AEC Category: Q200; Green_Lifecycle: Not Set; Green_REACh: Incomplete
signal-integrity model Cap
simulation model Cap
footprint 0805_HV
footprint 0805_HV1
footprint 0805
footprint 0805M
footprint 0805L
pins: 1, 2

## 08055A1R0CAT2A
designator C?  ValueDisplayed: 1pF  (hidden comment: 08055A1R0CAT2A)
CAP, CERM, 1 pF, 50 V,+/- 25%, C0G/NP0, 0805; Manufacturer: AVX; Polarized: N; CompType: Capacitor; Value: 1pF; U/M: EA; Cap_F: 0.000000000001; Tolerance_%: 25; ESR_ohm: 8.887; Value1: 8.887 ohm; VDC_V: 50; Value2: 50V; TaMin_C: -55; TaMax_C: 125; Cap_Case: 0805; SizeArea_mm2: 2.5; SizeAreaWB_mm2: 6.75; SizeX_mm: 2; SizeY_mm: 1.25; SizeZ_mm: 1.45; AEC Category: Q200; Green_Lifecycle: Not Set; Green_REACh: Incomplete
signal-integrity model Cap
simulation model Cap
footprint 0805_HV
footprint 0805_HV1
footprint 0805
footprint 0805M
footprint 0805L
pins: 1, 2

## 08055A1R2CAT2A
designator C?  ValueDisplayed: 1.2pF  (hidden comment: 08055A1R2CAT2A)
CAP, CERM, 1.2 pF, 50 V,+/- 21%, C0G/NP0, 0805; Manufacturer: AVX; Polarized: N; CompType: Capacitor; Value: 1.2pF; U/M: EA; Cap_F: 0.0000000000012; Tolerance_%: 21; ESR_ohm: 7.653; Value1: 7.653 ohm; VDC_V: 50; Value2: 50V; TaMin_C: -55; TaMax_C: 125; Cap_Case: 0805; SizeArea_mm2: 2.5; SizeAreaWB_mm2: 6.75; SizeX_mm: 2; SizeY_mm: 1.25; SizeZ_mm: 1.45; AEC Category: Q200; Green_Lifecycle: Not Set; Green_REACh: Incomplete
signal-integrity model Cap
simulation model Cap
footprint 0805_HV
footprint 0805_HV1
footprint 0805
footprint 0805M
footprint 0805L
pins: 1, 2

## 08055A1R5CAT2A
designator C?  ValueDisplayed: 1.5pF  (hidden comment: 08055A1R5CAT2A)
CAP, CERM, 1.5 pF, 50 V,+/- 17%, C0G/NP0, 0805; Manufacturer: AVX; Polarized: N; CompType: Capacitor; Value: 1.5pF; U/M: EA; Cap_F: 0.0000000000015; Tolerance_%: 17; ESR_ohm: 6.392; Value1: 6.392 ohm; VDC_V: 50; Value2: 50V; TaMin_C: -55; TaMax_C: 125; Cap_Case: 0805; SizeArea_mm2: 2.5; SizeAreaWB_mm2: 6.75; SizeX_mm: 2; SizeY_mm: 1.25; SizeZ_mm: 1.45; AEC Category: Q200; Green_Lifecycle: Not Set; Green_REACh: Incomplete
signal-integrity model Cap
simulation model Cap
footprint 0805_HV
footprint 0805_HV1
footprint 0805
footprint 0805M
footprint 0805L
pins: 1, 2

## 08055A1R8CAT2A
designator C?  ValueDisplayed: 1.8pF  (hidden comment: 08055A1R8CAT2A)
CAP, CERM, 1.8 pF, 50 V,+/- 14%, C0G/NP0, 0805; Manufacturer: AVX; Polarized: N; CompType: Capacitor; Value: 1.8pF; U/M: EA; Cap_F: 0.0000000000018; Tolerance_%: 14; ESR_ohm: 5.53; Value1: 5.53 ohm; VDC_V: 50; Value2: 50V; TaMin_C: -55; TaMax_C: 125; Cap_Case: 0805; SizeArea_mm2: 2.5; SizeAreaWB_mm2: 6.75; SizeX_mm: 2; SizeY_mm: 1.25; SizeZ_mm: 1.45; AEC Category: Q200; Green_Lifecycle: Not Set; Green_REACh: Incomplete
signal-integrity model Cap
simulation model Cap
footprint 0805_HV
footprint 0805_HV1
footprint 0805
footprint 0805M
footprint 0805L
pins: 1, 2

## 08055A2R2CAT2A
designator C?  ValueDisplayed: 2.2pF  (hidden comment: 08055A2R2CAT2A)
CAP, CERM, 2.2 pF, 50 V,+/- 11%, C0G/NP0, 0805; Manufacturer: AVX; Polarized: N; CompType: Capacitor; Value: 2.2pF; U/M: EA; Cap_F: 0.0000000000022; Tolerance_%: 11; ESR_ohm: 4.726; Value1: 4.726 ohm; VDC_V: 50; Value2: 50V; TaMin_C: -55; TaMax_C: 125; Cap_Case: 0805; SizeArea_mm2: 2.5; SizeAreaWB_mm2: 6.75; SizeX_mm: 2; SizeY_mm: 1.25; SizeZ_mm: 1.45; AEC Category: Q200; Green_Lifecycle: Not Set; Green_REACh: Incomplete
signal-integrity model Cap
simulation model Cap
footprint 0805_HV
footprint 0805_HV1
footprint 0805
footprint 0805M
footprint 0805L
pins: 1, 2

## 08055A2R7CAT2A
designator C?  ValueDisplayed: 2.7pF  (hidden comment: 08055A2R7CAT2A)
CAP, CERM, 2.7 pF, 50 V,+/- 9%, C0G/NP0, 0805; Manufacturer: AVX; Polarized: N; CompType: Capacitor; Value: 2.7pF; U/M: EA; Cap_F: 0.0000000000027; Tolerance_%: 9; ESR_ohm: 4.036; Value1: 4.036 ohm; VDC_V: 50; Value2: 50V; TaMin_C: -55; TaMax_C: 125; Cap_Case: 0805; SizeArea_mm2: 2.5; SizeAreaWB_mm2: 6.75; SizeX_mm: 2; SizeY_mm: 1.25; SizeZ_mm: 1.45; AEC Category: Q200; Green_Lifecycle: Not Set; Green_REACh: Incomplete
signal-integrity model Cap
simulation model Cap
footprint 0805_HV
footprint 0805_HV1
footprint 0805
footprint 0805M
footprint 0805L
pins: 1, 2

## 08055A3R3CAT2A
designator C?  ValueDisplayed: 3.3pF  (hidden comment: 08055A3R3CAT2A)
CAP, CERM, 3.3 pF, 50 V,+/- 8%, C0G/NP0, 0805; Manufacturer: AVX; Polarized: N; CompType: Capacitor; Value: 3.3pF; U/M: EA; Cap_F: 0.0000000000033; Tolerance_%: 8; ESR_ohm: 3.467; Value1: 3.467 ohm; VDC_V: 50; Value2: 50V; TaMin_C: -55; TaMax_C: 125; Cap_Case: 0805; SizeArea_mm2: 2.5; SizeAreaWB_mm2: 6.75; SizeX_mm: 2; SizeY_mm: 1.25; SizeZ_mm: 1.45; AEC Category: Q200; Green_Lifecycle: Not Set; Green_REACh: Incomplete
signal-integrity model Cap
simulation model Cap
footprint 0805_HV
footprint 0805_HV1
footprint 0805
footprint 0805M
footprint 0805L
pins: 1, 2

## 08055A3R9CAT2A
designator C?  ValueDisplayed: 3.9pF  (hidden comment: 08055A3R9CAT2A)
CAP, CERM, 3.9 pF, 50 V,+/- 6%, C0G/NP0, 0805; Manufacturer: AVX; Polarized: N; CompType: Capacitor; Value: 3.9pF; U/M: EA; Cap_F: 0.0000000000039; Tolerance_%: 6; ESR_ohm: 3.061; Value1: 3.061 ohm; VDC_V: 50; Value2: 50V; TaMin_C: -55; TaMax_C: 125; Cap_Case: 0805; SizeArea_mm2: 2.5; SizeAreaWB_mm2: 6.75; SizeX_mm: 2; SizeY_mm: 1.25; SizeZ_mm: 1.45; AEC Category: Q200; Green_Lifecycle: Not Set; Green_REACh: Incomplete
signal-integrity model Cap
simulation model Cap
footprint 0805_HV
footprint 0805_HV1
footprint 0805
footprint 0805M
footprint 0805L
pins: 1, 2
